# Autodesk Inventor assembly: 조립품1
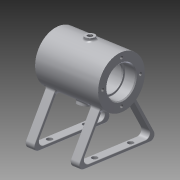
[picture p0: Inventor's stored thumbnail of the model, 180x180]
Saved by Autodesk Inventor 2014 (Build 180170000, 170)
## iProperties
Created: 2016-03
Part Number: 조립품1
Document SubType Name: Assembly
Designer: 703-15
Author: 703-15
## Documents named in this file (2)
- C:\Users\703-15\Desktop\460308V1008\조립품1.iam
- C:\Users\703-15\Desktop\460308V1008\본체.ipt
